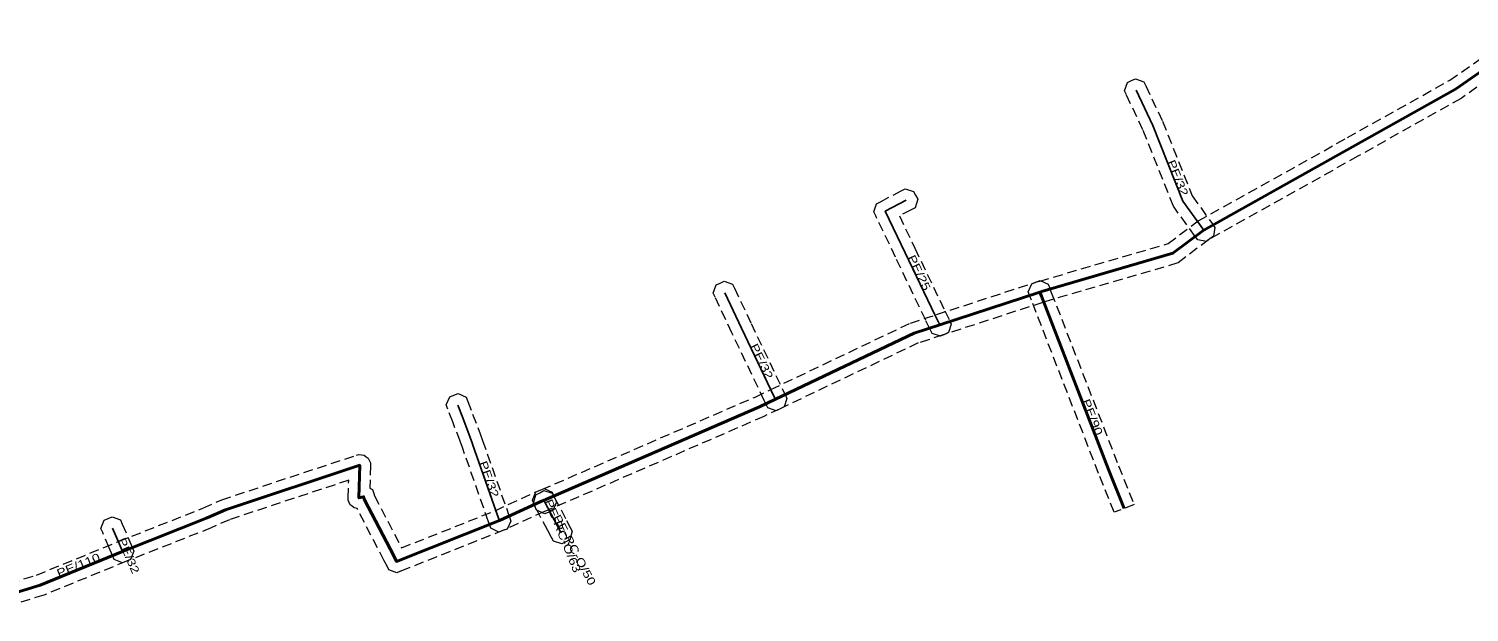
# Model space of a CAD drawing. Extents: x -772780 to -772236, y -1033108 to -1032817.
# Drawn here: x -772506.2 to -772371.2, y -1032984.4 to -1032929.7 of the extents above; entities that cross this region are included whole.
import ezdxf

# ---------------------------------------------------------------- set-up
doc = ezdxf.new("R2010")
doc.units = 0
doc.header["$LTSCALE"] = 0.3
doc.linetypes.add('MEDIUM_DASHED', pattern=[4.5, 3, -1.5])
doc.layers.add('1', color=7, linetype='MEDIUM_DASHED', lineweight=13)
doc.layers.add('24', color=7, linetype='Continuous', lineweight=25)
doc.layers.add('30', color=7, linetype='Continuous')

msp = doc.modelspace()

# ---------------------------------------------------------------- linework, layer by layer
at = {"layer": '1'}
for points in [[(-772510.535, -1032982.463), (-772505.481, -1032980.902), (-772497.803, -1032977.762), (-772489.879, -1032974.634), (-772488.129, -1032973.849), (-772475.5, -1032969.672), (-772475.268, -1032969.595), (-772474.786, -1032969.672), (-772474.59, -1032969.818), (-772474.393, -1032969.964), (-772474.179, -1032970.404), (-772474.186, -1032970.648), (-772474.242, -1032972.755), (-772473.987, -1032972.899), (-772473.869, -1032973.276), (-772473.807, -1032973.473), (-772471.265, -1032978.358), (-772462.496, -1032974.872), (-772458.688, -1032973.122), (-772458.294, -1032972.962), (-772458.138, -1032972.898), (-772438.149, -1032964.226), (-772436.669, -1032963.521), (-772423.593, -1032957.299), (-772421.15, -1032956.503), (-772411.762, -1032953.445), (-772411.475, -1032953.36), (-772399.443, -1032949.847), (-772396.76, -1032947.823), (-772396.609, -1032947.729), (-772382.64, -1032939.922), (-772373.053, -1032934.543), (-772366.11, -1032929.725)], [(-772364.95, -1032931.355), (-772371.991, -1032936.241), (-772381.662, -1032941.668), (-772395.591, -1032949.451), (-772395.626, -1032949.473), (-772398.531, -1032951.665), (-772410.913, -1032955.28), (-772411.17, -1032955.355), (-772420.53, -1032958.405), (-772422.851, -1032959.161), (-772435.809, -1032965.327), (-772437.321, -1032966.046), (-772457.362, -1032974.742), (-772457.54, -1032974.814), (-772457.892, -1032974.958), (-772461.708, -1032976.712), (-772471.369, -1032980.551), (-772471.728, -1032980.694), (-772472.452, -1032980.422), (-772472.628, -1032980.078), (-772472.89, -1032979.566), (-772475.439, -1032974.669), (-772475.716, -1032974.606), (-772475.897, -1032974.459), (-772476.079, -1032974.312), (-772476.274, -1032973.888), (-772476.268, -1032973.655), (-772476.224, -1032972.018), (-772487.403, -1032975.715), (-772489.101, -1032976.478), (-772497.057, -1032979.618), (-772504.807, -1032982.786), (-772509.975, -1032984.383)]]:
    msp.add_lwpolyline(points, dxfattribs=at)
for points in [[(-772396.669, -1032949.511), (-772396.911, -1032949.175), (-772398.943, -1032946.355), (-772401.798, -1032939.189), (-772403.345, -1032935.906), (-772403.521, -1032935.532), (-772403.241, -1032934.752), (-772402.866, -1032934.575), (-772402.492, -1032934.399), (-772401.712, -1032934.679), (-772401.535, -1032935.054), (-772399.962, -1032938.391), (-772397.177, -1032945.385), (-772395.289, -1032948.005), (-772395.047, -1032948.341), (-772395.179, -1032949.159), (-772395.515, -1032949.401), (-772395.851, -1032949.643)], [(-772421.563, -1032958.26), (-772421.742, -1032957.886), (-772422.157, -1032957.019), (-772424.979, -1032951.134), (-772426.843, -1032947.245), (-772427.017, -1032946.881), (-772426.762, -1032946.114), (-772426.404, -1032945.927), (-772424.446, -1032944.903), (-772424.079, -1032944.711), (-772423.289, -1032944.959), (-772423.097, -1032945.326), (-772422.905, -1032945.693), (-772423.153, -1032946.483), (-772423.52, -1032946.675), (-772424.622, -1032947.252), (-772423.175, -1032950.27), (-772420.353, -1032956.155), (-772419.938, -1032957.022), (-772419.759, -1032957.396), (-772420.034, -1032958.177), (-772420.408, -1032958.356), (-772420.782, -1032958.535)], [(-772436.962, -1032965.23), (-772437.141, -1032964.856), (-772437.282, -1032964.562), (-772440.324, -1032958.198), (-772441.885, -1032954.875), (-772442.061, -1032954.5), (-772441.78, -1032953.721), (-772441.405, -1032953.545), (-772441.03, -1032953.369), (-772440.251, -1032953.65), (-772440.075, -1032954.025), (-772438.516, -1032957.342), (-772435.478, -1032963.698), (-772435.337, -1032963.992), (-772435.158, -1032964.365), (-772435.433, -1032965.147), (-772435.807, -1032965.326), (-772436.18, -1032965.505)], [(-772402.622, -1032974.308), (-772404.494, -1032975.012), (-772405.948, -1032971.394), (-772412.249, -1032955.149), (-772412.399, -1032954.761), (-772412.548, -1032954.375), (-772412.213, -1032953.617), (-772411.827, -1032953.467), (-772411.441, -1032953.318), (-772410.683, -1032953.653), (-772410.533, -1032954.039), (-772410.383, -1032954.427), (-772404.088, -1032970.66)], [(-772462.908, -1032976.514), (-772463.045, -1032976.123), (-772463.123, -1032975.902), (-772465.57, -1032968.948), (-772465.778, -1032968.356), (-772466.479, -1032966.541), (-772466.939, -1032965.348), (-772467.088, -1032964.962), (-772466.752, -1032964.204), (-772466.366, -1032964.055), (-772465.98, -1032963.906), (-772465.222, -1032964.242), (-772465.073, -1032964.628), (-772464.613, -1032965.821), (-772463.902, -1032967.664), (-772463.684, -1032968.284), (-772461.237, -1032975.238), (-772461.159, -1032975.461), (-772461.021, -1032975.852), (-772461.38, -1032976.598), (-772461.771, -1032976.735), (-772462.162, -1032976.873)], [(-772457.146, -1032973.128), (-772456.99, -1032973.512), (-772456.915, -1032973.697), (-772456.76, -1032974.081), (-772457.082, -1032974.844), (-772457.466, -1032975), (-772457.85, -1032975.155), (-772458.613, -1032974.833), (-772458.769, -1032974.449), (-772458.844, -1032974.264), (-772458.999, -1032973.88), (-772458.677, -1032973.117), (-772458.293, -1032972.961), (-772457.909, -1032972.806)], [(-772457.041, -1032977.736), (-772457.234, -1032977.37), (-772457.577, -1032976.722), (-772458.727, -1032974.539), (-772458.92, -1032974.173), (-772458.675, -1032973.381), (-772458.308, -1032973.188), (-772457.942, -1032972.995), (-772457.15, -1032973.24), (-772456.957, -1032973.607), (-772455.807, -1032975.788), (-772455.466, -1032976.436), (-772455.273, -1032976.803), (-772455.517, -1032977.594), (-772455.883, -1032977.787), (-772456.25, -1032977.98)], [(-772498.188, -1032979.462), (-772498.35, -1032979.081), (-772498.659, -1032978.353), (-772499.278, -1032976.915), (-772499.442, -1032976.535), (-772499.136, -1032975.766), (-772498.755, -1032975.602), (-772498.375, -1032975.438), (-772497.606, -1032975.744), (-772497.442, -1032976.125), (-772496.821, -1032977.567), (-772496.51, -1032978.299), (-772496.348, -1032978.68), (-772496.658, -1032979.448), (-772497.039, -1032979.61), (-772497.42, -1032979.772)]]:
    msp.add_lwpolyline(points, close=True, dxfattribs=at)
at = {"layer": '24'}
msp.add_line((-772457.917, -1032973.888), (-772457.842, -1032974.073), dxfattribs=at)
at = {"layer": '24', "lineweight": 40}
for points in [[(-772365.53, -1032930.54), (-772372.522, -1032935.392), (-772382.151, -1032940.795), (-772396.1, -1032948.59), (-772396.193, -1032948.648), (-772398.987, -1032950.756), (-772411.194, -1032954.32), (-772411.466, -1032954.4), (-772420.84, -1032957.454), (-772423.222, -1032958.23), (-772436.239, -1032964.424), (-772437.735, -1032965.136), (-772457.75, -1032973.82), (-772457.917, -1032973.888), (-772458.29, -1032974.04), (-772462.102, -1032975.792), (-772471.738, -1032979.622), (-772472.002, -1032979.107), (-772474.735, -1032973.856), (-772474.823, -1032973.575), (-772475.268, -1032973.682), (-772475.186, -1032970.621), (-772487.766, -1032974.782), (-772489.49, -1032975.556), (-772497.43, -1032978.69), (-772505.144, -1032981.844), (-772510.255, -1032983.423)], [(-772411.466, -1032954.4), (-772411.316, -1032954.788), (-772405.018, -1032971.027), (-772403.558, -1032974.66)]]:
    msp.add_lwpolyline(points, dxfattribs=at)
at = {"layer": '24'}
for points in [[(-772396.1, -1032948.59), (-772398.06, -1032945.87), (-772400.88, -1032938.79), (-772402.44, -1032935.48)], [(-772420.84, -1032957.454), (-772421.255, -1032956.587), (-772424.077, -1032950.702), (-772425.941, -1032946.813), (-772423.983, -1032945.789)], [(-772436.239, -1032964.424), (-772436.38, -1032964.13), (-772439.42, -1032957.77), (-772440.98, -1032954.45)], [(-772462.102, -1032975.792), (-772462.18, -1032975.57), (-772464.621, -1032968.636), (-772464.627, -1032968.616), (-772464.84, -1032968.01), (-772465.545, -1032966.18), (-772466.006, -1032964.988)], [(-772456.35, -1032976.903), (-772456.692, -1032976.255), (-772457.842, -1032974.073)], [(-772497.43, -1032978.69), (-772497.739, -1032977.959), (-772498.36, -1032976.52)]]:
    msp.add_lwpolyline(points, dxfattribs=at)

# ---------------------------------------------------------------- texts
at = {"layer": '30', "width": 1.3}
for s, rotation, p in [('PE/32', 291.718, (-772399.527, -1032942.187)), ('PE/25', 295.619, (-772423.868, -1032951.137)), ('PE/32', 295.547, (-772438.62, -1032959.442)), ('PE/90', 291.198, (-772407.516, -1032964.585)), ('PE/32', 289.394, (-772464.009, -1032970.373)), ('PE-RC-O/63', 292.068, (-772457.879, -1032973.98)), ('PE-RC-O/50', 297.791, (-772457.096, -1032975.488)), ('PE/32', 293.343, (-772497.892, -1032977.604)), ('PE/110', 22.238, (-772503.397, -1032981.129))]:
    msp.add_text(s, height=0.75, rotation=rotation, dxfattribs=at).set_placement(p)

doc.saveas('drawing.dxf')
